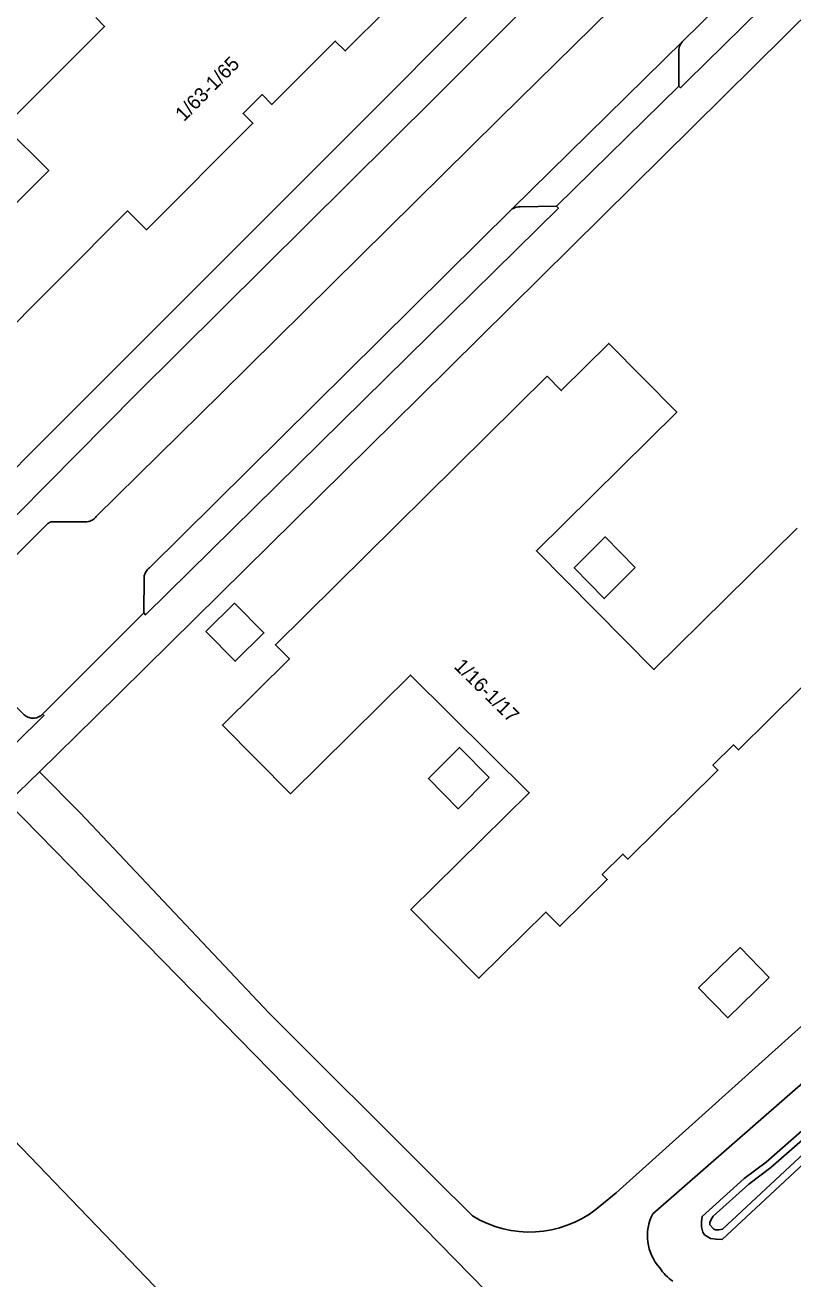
# Model space of a CAD drawing. Extents: x 162791 to 163827, y 385795 to 386523.
# Drawn here: x 163089.2 to 163143.1, y 386026.9 to 386115 of the extents above; entities that cross this region are included whole.
import ezdxf

# ---------------------------------------------------------------- set-up
doc = ezdxf.new("R2010")
doc.units = 0
for name, color, linetype in [('IMGEO_Grasland_overig', 7, 'Continuous'), ('IMGEO_Pand', 7, 'Continuous'), ('IMGEO_Pand_nummerreeks', 7, 'Continuous'), ('IMGEO_Parkeervlak_open', 7, 'Continuous'), ('IMGEO_Rijbaan_lokaal_gesloten', 7, 'Continuous'), ('IMGEO_Waterloop', 7, 'Continuous'), ('IMGEO_Woonerf_gesloten', 7, 'Continuous'), ('IMGEO_Woonerf_open', 7, 'Continuous')]:
    doc.layers.add(name, color=color, linetype=linetype)

msp = doc.modelspace()

# ---------------------------------------------------------------- linework, layer by layer
at = {"layer": 'IMGEO_Grasland_overig'}
msp.add_lwpolyline([(163145.656, 386039.012), (163141.245, 386035.148), (163139.702, 386033.993), (163136.754, 386031.335), (163136.703, 386030.967), (163136.703, 386030.604), (163136.805, 386030.22), (163136.909, 386030.048), (163137.336, 386029.787), (163137.723, 386029.721), (163138.145, 386029.699), (163148.997, 386039.8)], dxfattribs=at)
at = {"layer": 'IMGEO_Pand'}
for points in [[(163086.012, 386099.882), (163090.889, 386104.76), (163087.791, 386107.857), (163094.812, 386114.879), (163094.19, 386115.501)], [(163114.7, 386116.158), (163111.698, 386113.155), (163110.998, 386113.855), (163106.548, 386109.404), (163105.857, 386110.094), (163104.531, 386108.768), (163105.221, 386108.078), (163097.748, 386100.603), (163096.425, 386101.925), (163086.649, 386092.147)], [(163145.83, 386070.54), (163139.3, 386064.088), (163138.953, 386064.438), (163137.507, 386063.009), (163137.853, 386062.658), (163131.536, 386056.417), (163131.19, 386056.767), (163129.743, 386055.338), (163130.09, 386054.987), (163126.763, 386051.7), (163125.779, 386052.696), (163121.082, 386048.054), (163116.31, 386052.871), (163124.617, 386061.079), (163116.284, 386069.342), (163107.849, 386061.007), (163103.083, 386065.83), (163107.785, 386070.475), (163106.801, 386071.471), (163125.865, 386090.318), (163126.854, 386089.317), (163130.198, 386092.621), (163134.963, 386087.798), (163125.119, 386078.071), (163133.366, 386069.724), (163143.424, 386079.662)], [(163132.041, 386076.88), (163129.874, 386074.708), (163127.777, 386076.862), (163129.94, 386079.033), (163132.041, 386076.88)], [(163101.922, 386072.392), (163103.98, 386070.31), (163105.989, 386072.295), (163103.931, 386074.377), (163101.922, 386072.392)], [(163121.809, 386062.144), (163119.615, 386059.957), (163117.538, 386062.084), (163119.713, 386064.262), (163121.809, 386062.144)], [(163141.454, 386048.102), (163138.549, 386045.273), (163136.502, 386047.374), (163139.407, 386050.204), (163141.454, 386048.102)], [(163100.049, 386024.635), (163081.98, 386043.39), (163082.601, 386043.999), (163082.342, 386044.263), (163078.117, 386040.121)]]:
    msp.add_lwpolyline(points, dxfattribs=at)
at = {"layer": 'IMGEO_Parkeervlak_open'}
for points in [[(163135.419, 386113.879), (163123.392, 386102.042)], [(163135.116, 386110.686), (163135.122, 386113.292), (163135.142, 386113.385), (163135.17, 386113.476), (163135.206, 386113.565), (163135.249, 386113.65), (163135.299, 386113.731), (163135.356, 386113.808), (163135.419, 386113.879)], [(163135.116, 386110.686), (163126.525, 386102.25)], [(163123.392, 386102.042), (163123.467, 386102.089), (163123.546, 386102.129), (163123.629, 386102.162), (163123.714, 386102.186), (163123.802, 386102.203), (163123.89, 386102.211), (163123.979, 386102.211), (163126.525, 386102.25)]]:
    msp.add_lwpolyline(points, dxfattribs=at)
at = {"layer": 'IMGEO_Rijbaan_lokaal_gesloten'}
for points in [[(163133.296, 386031.516), (163151.762, 386047.67), (163185.549, 386078.284), (163199.323, 386090.951), (163200.984, 386088.924), (163204.985, 386084.042), (163205.132, 386083.984), (163206.676, 386083.379)], [(163129.316, 386031.834), (163130.711, 386032.995), (163156.731, 386056.38), (163168.437, 386066.688), (163193.001, 386088.975)], [(163090.229, 386062.548), (163088.018, 386060.382)], [(163090.229, 386062.548), (163093.084, 386059.675), (163106.347, 386045.615), (163117.907, 386034.052), (163120.625, 386031.361)], [(163088.018, 386060.382), (163122.643, 386025)]]:
    msp.add_lwpolyline(points, dxfattribs=at)
for centre, radius, start, end in [((163124.628, 386037.886), 7.655, 238.4692, 307.7612), ((163136.215, 386029.958), 3.309, 151.90734, 222.69125), ((163136.2, 386029.175), 2.824, 211.14826, 237.92213)]:
    msp.add_arc(centre, radius, start, end, dxfattribs=at)
at = {"layer": 'IMGEO_Waterloop'}
msp.add_lwpolyline([(163148.646, 386040.168), (163138.178, 386030.424), (163137.93, 386030.383), (163137.692, 386030.39), (163137.563, 386030.434), (163137.295, 386030.735), (163137.289, 386030.896), (163137.378, 386031.12), (163137.526, 386031.346), (163140.025, 386033.6), (163141.565, 386034.753), (163146.004, 386038.641)], dxfattribs=at)
at = {"layer": 'IMGEO_Woonerf_gesloten'}
for points in [[(163160.511, 386152.137), (163160.792, 386152.325), (163161.786, 386152.232), (163167.195, 386143.822), (163167.248, 386143.629), (163167.285, 386143.433), (163167.305, 386143.234), (163167.307, 386143.034), (163167.293, 386142.834), (163167.262, 386142.636), (163167.214, 386142.442), (163167.15, 386142.253), (163167.069, 386142.069), (163166.974, 386141.894), (163166.863, 386141.727), (163166.739, 386141.57), (163166.602, 386141.424), (163135.695, 386111.044), (163135.224, 386110.578), (163135.116, 386110.686)], [(163078.625, 386073.903), (163090.945, 386086.246), (163109.567, 386104.883), (163137.817, 386133.231), (163155.341, 386150.644)], [(163083.469, 386068.773), (163082.458, 386069.732), (163081.902, 386070.419), (163081.777, 386070.695), (163081.677, 386070.98), (163081.602, 386071.274), (163081.553, 386071.573), (163081.53, 386071.874), (163081.534, 386072.177), (163081.564, 386072.478), (163081.621, 386072.776), (163081.703, 386073.067), (163081.81, 386073.35), (163081.942, 386073.623), (163082.097, 386073.883), (163082.274, 386074.129), (163082.472, 386074.358), (163097.035, 386089.065), (163117.963, 386109.833), (163142.941, 386134.855), (163156.619, 386148.636)], [(163144.69, 386116.333), (163116.889, 386088.826), (163094.139, 386066.379), (163090.229, 386062.548)], [(163126.525, 386102.25), (163126.659, 386102.115), (163125.212, 386100.685), (163097.687, 386073.563), (163097.552, 386073.701)], [(163097.552, 386073.701), (163090.455, 386066.592)], [(163090.455, 386066.592), (163090.544, 386066.502), (163088.52, 386064.502), (163087.864, 386064.604), (163086.067, 386066.309)]]:
    msp.add_lwpolyline(points, dxfattribs=at)
at = {"layer": 'IMGEO_Woonerf_open'}
for points in [[(163160.511, 386152.137), (163161.586, 386150.349), (163162.28, 386149.265), (163162.573, 386148.391), (163162.789, 386147.496), (163162.928, 386146.585), (163162.987, 386145.665), (163162.968, 386144.743), (163162.869, 386143.827), (163162.691, 386142.923), (163162.437, 386142.037), (163162.107, 386141.177), (163161.705, 386140.347), (163161.232, 386139.556), (163160.694, 386138.808), (163160.093, 386138.11), (163135.419, 386113.879)], [(163083.905, 386073.107), (163090.682, 386079.841), (163090.704, 386079.865), (163090.727, 386079.887), (163090.752, 386079.91), (163090.778, 386079.933), (163090.804, 386079.954), (163090.832, 386079.975), (163090.86, 386079.995), (163090.889, 386080.014), (163090.917, 386080.032), (163090.946, 386080.049), (163090.974, 386080.064), (163091.002, 386080.077), (163091.029, 386080.088), (163093.415, 386080.108), (163093.492, 386080.104), (163093.569, 386080.106), (163093.646, 386080.114), (163093.721, 386080.13), (163093.795, 386080.151), (163093.867, 386080.179), (163093.937, 386080.212), (163094.003, 386080.252), (163094.066, 386080.296), (163094.124, 386080.346), (163094.179, 386080.401), (163094.228, 386080.46), (163102.959, 386089.088), (163122.487, 386108.369), (163123.874, 386109.738), (163156.292, 386141.593)], [(163097.552, 386073.701), (163097.579, 386076.216), (163097.595, 386076.301), (163097.618, 386076.383), (163097.648, 386076.464), (163097.685, 386076.542), (163097.728, 386076.616), (163097.776, 386076.687), (163097.831, 386076.753), (163097.891, 386076.815), (163097.956, 386076.871), (163123.392, 386102.042)], [(163086.067, 386066.309), (163087.688, 386068.031), (163089.165, 386066.555), (163089.226, 386066.504), (163089.29, 386066.458), (163089.359, 386066.418), (163089.43, 386066.383), (163089.505, 386066.355), (163089.581, 386066.334), (163089.659, 386066.319), (163089.738, 386066.311), (163089.817, 386066.31), (163089.897, 386066.316), (163089.975, 386066.328), (163090.052, 386066.347), (163090.127, 386066.373), (163090.2, 386066.405), (163090.269, 386066.443), (163090.335, 386066.487), (163090.397, 386066.537), (163090.455, 386066.592)]]:
    msp.add_lwpolyline(points, dxfattribs=at)

# ---------------------------------------------------------------- texts
at = {"layer": 'IMGEO_Pand_nummerreeks'}
for s, rotation, p in [('1/63-1/65', 45.28455, (163100.373, 386108.151)), ('1/16-1/17', 315.39025, (163119.274, 386069.884))]:
    msp.add_text(s, height=1, rotation=rotation, dxfattribs=at).set_placement(p)

doc.saveas('drawing.dxf')
